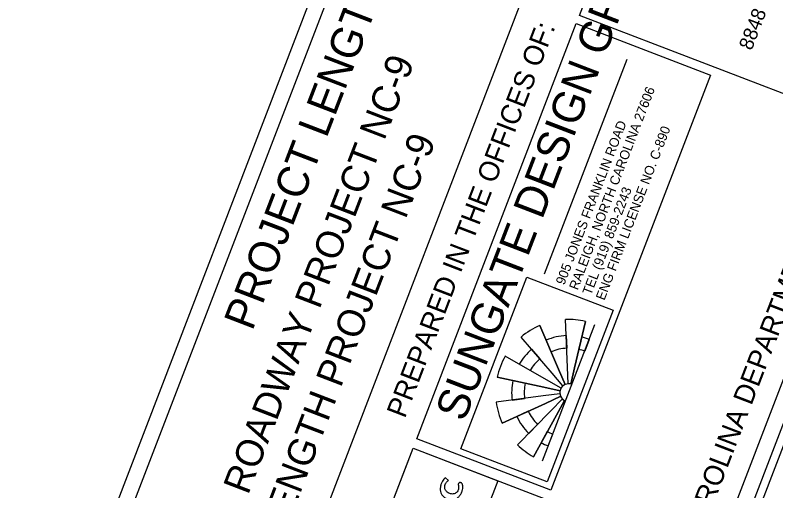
# Model space of a CAD drawing. Extents: x 1015221 to 1064345, y 619216 to 647967.
# Drawn here: x 1023380 to 1025328, y 637598 to 638817 of the extents above; entities that cross this region are included whole.
import ezdxf

# ---------------------------------------------------------------- set-up
doc = ezdxf.new("R2010")
doc.units = 0
for name, color, linetype in [('Old_Level_8', 7, 'Continuous'), ('Scratch_Level_0', 7, 'Continuous'), ('Sheet Data Field CELL', 7, 'Continuous'), ('Sheet Data Text CELL', 7, 'Continuous'), ('Sheet Plot Border Inside CELL', 7, 'Continuous'), ('Sheet Title CELL', 7, 'Continuous')]:
    doc.layers.add(name, color=color, linetype=linetype)

msp = doc.modelspace()

# ---------------------------------------------------------------- linework, layer by layer
at = {"layer": 'Scratch_Level_0'}
msp.add_lwpolyline([(1024162.8, 637091.4), (1024399.4, 637707.4), (1024616.1, 637624.1), (1024379.4, 637008.1)], close=True, dxfattribs=at)
at = {"layer": 'Sheet Data Text CELL'}
for p, q in [((1024736.3, 638154.5), (1024947.4, 638704)), ((1024772.1, 637909.9), (1024724, 638022)), ((1024724, 638022), (1024772.1, 637909.9)), ((1024730.7, 637674.8), (1024865.1, 638024.7)), ((1024795.1, 637915.2), (1024790, 638037)), ((1024795.1, 637915.2), (1024790, 638037)), ((1024812.8, 637913.5), (1024840.7, 638032.2)), ((1024840.7, 638032.2), (1024812.8, 637913.5)), ((1024755.3, 637899.5), (1024676.1, 637992.2)), ((1024755.3, 637899.5), (1024676.1, 637992.2)), ((1024753, 637954.4), (1024740.3, 637984.1)), ((1024791.8, 637995.8), (1024793.1, 637963.6)), ((1024823.9, 637960.7), (1024831.2, 637992)), ((1024850.3, 637986.2), (1024838.8, 637956.1)), ((1024702.9, 637960.8), (1024723.9, 637936.3)), ((1024741.1, 637882.3), (1024635.4, 637943)), ((1024741.1, 637882.3), (1024635.4, 637943)), ((1024699.1, 637906.5), (1024671.1, 637922.5)), ((1024772.1, 637909.9), (1024789, 637870.6)), ((1024789, 637870.6), (1024772.1, 637909.9)), ((1024796.9, 637872.4), (1024795.1, 637915.2)), ((1024796.9, 637872.4), (1024795.1, 637915.2)), ((1024812.8, 637913.5), (1024803.1, 637871.8)), ((1024803.1, 637871.8), (1024812.8, 637913.5)), ((1024733.9, 637863.6), (1024614.7, 637889.3)), ((1024614.7, 637889.3), (1024733.9, 637863.6)), ((1024778.3, 637861), (1024741.1, 637882.3)), ((1024778.3, 637861), (1024741.1, 637882.3)), ((1024783.2, 637867), (1024755.3, 637899.5)), ((1024783.2, 637867), (1024755.3, 637899.5)), ((1024686.5, 637873.8), (1024655, 637880.6)), ((1024733.9, 637863.6), (1024775.8, 637854.5)), ((1024775.8, 637854.5), (1024733.9, 637863.6)), ((1024775.4, 637846.8), (1024732.9, 637841.2)), ((1024775.4, 637846.8), (1024732.9, 637841.2)), ((1024732.9, 637841.2), (1024612.1, 637825.5)), ((1024732.9, 637841.2), (1024612.1, 637825.5)), ((1024653, 637830.8), (1024684.9, 637835)), ((1024738.4, 637822.3), (1024777.3, 637840.3)), ((1024777.3, 637840.3), (1024738.4, 637822.3)), ((1024782, 637833.6), (1024752, 637803)), ((1024782, 637833.6), (1024752, 637803)), ((1024766.3, 637792.4), (1024787, 637829.9)), ((1024787, 637829.9), (1024766.3, 637792.4)), ((1024738.4, 637822.3), (1024627.7, 637771.3)), ((1024627.7, 637771.3), (1024738.4, 637822.3)), ((1024694.4, 637802.1), (1024665.2, 637788.6)), ((1024752, 637803), (1024666.7, 637715.9)), ((1024752, 637803), (1024666.7, 637715.9)), ((1024766.3, 637792.4), (1024707.5, 637685.6)), ((1024707.5, 637685.6), (1024766.3, 637792.4)), ((1024695.6, 637745.4), (1024718.1, 637768.4)), ((1024742.9, 637749.9), (1024727.4, 637721.7)), ((1024745.5, 637713.3), (1024757, 637743.4)), ((1024490.3, 637625), (1024482.3, 637631.8))]:
    msp.add_line(p, q, dxfattribs=at)
for points in [[(1024825.5, 638816.3), (1025062.2, 639432.5), (1025713.1, 639182.4), (1025476.4, 638566.2)], [(1024408.7, 637731.4), (1024817.4, 638795.4), (1025160.7, 638663.5), (1024751.9, 637599.5)], [(1024521.6, 637705.7), (1024690.5, 638145.5), (1024911.4, 638060.7), (1024742.5, 637620.9)], [(1024162.7, 637091.2), (1024399.4, 637707.4), (1025050.3, 637457.3), (1024813.6, 636841.1)]]:
    msp.add_lwpolyline(points, close=True, dxfattribs=at)
for radius, start, end in [(187.4, 113.2233, 130.5211), (187.4, 113.2233, 130.5211), (187.4, 76.8097, 92.4104), (187.4, 76.8097, 92.4104), (146.2, 92.4104, 113.2233), (146.2, 92.4104, 113.2233), (146.2, 68.983, 76.8097), (146.2, 68.983, 76.8097), (146.2, 130.5211, 150.1448), (146.2, 130.5211, 150.1448), (113.9, 92.4104, 113.2233), (113.9, 92.4104, 113.2233), (113.9, 68.983, 76.8097), (113.9, 68.983, 76.8097), (187.4, 150.1448, 167.8212), (187.4, 150.1448, 167.8212), (113.9, 130.5211, 150.1448), (113.9, 130.5211, 150.1448), (146.2, 167.8212, 187.445), (146.2, 167.8212, 187.445), (113.9, 167.8212, 187.445), (113.9, 167.8212, 187.445), (22.7, 68.983, 248.983), (22.7, 113.2233, 130.5211), (22.7, 76.8097, 92.4104), (22.7, 187.445, 204.7427), (22.7, 150.1448, 167.8212), (187.4, 187.445, 204.7427), (187.4, 187.445, 204.7427), (22.7, 225.5557, 241.1563), (146.2, 204.7427, 225.5557), (146.2, 204.7427, 225.5557), (113.9, 204.7427, 225.5557), (113.9, 204.7427, 225.5557), (113.9, 241.1563, 248.983), (113.9, 241.1563, 248.983), (187.4, 225.5557, 241.1563), (187.4, 225.5557, 241.1563), (146.2, 241.1563, 248.983), (146.2, 241.1563, 248.983)]:
    msp.add_arc((1024797.9, 637849.7), radius, start, end, dxfattribs=at)
msp.add_open_spline([(1024482.3, 637631.8), (1024481.1, 637630.8), (1024478.3, 637628.5), (1024474.6, 637623.3), (1024471.1, 637616.4), (1024469, 637608.4), (1024468.6, 637600.2), (1024470.3, 637592.6), (1024474.1, 637586.1), (1024479.4, 637581), (1024486.1, 637577.3), (1024493.5, 637575.1), (1024500.9, 637575.1), (1024507.2, 637576.8), (1024513.4, 637580.2), (1024519.3, 637585.8), (1024523.7, 637593.4), (1024526, 637601), (1024526.8, 637607.8), (1024526.4, 637613.5), (1024524.6, 637617.8), (1024521.7, 637619.1), (1024519.5, 637619.7), (1024517.6, 637618.7), (1024516.1, 637617.6), (1024515.4, 637616), (1024514.9, 637613.6), (1024515.8, 637611), (1024515.9, 637607.6), (1024516.2, 637604.2), (1024514.9, 637600), (1024512.9, 637595.8), (1024509, 637592.5), (1024504.7, 637590.6), (1024500, 637589.6), (1024495.3, 637590.5), (1024490.7, 637591.6), (1024486.8, 637594.5), (1024483.5, 637597.7), (1024481.3, 637601.4), (1024480.2, 637605.6), (1024480.2, 637609.9), (1024481.5, 637614.5), (1024483.6, 637618.8), (1024486.6, 637622.5), (1024489.1, 637624.2), (1024490.3, 637625)], degree=3, dxfattribs=at)
at = {"layer": 'Sheet Plot Border Inside CELL'}
msp.add_lwpolyline([(1023304.8, 632396.8), (1028086.2, 644841.8), (1020206.9, 647869.1), (1015425.5, 635424)], close=True, dxfattribs=at)
at = {"layer": 'Sheet Title CELL'}
for p, q in [((1022495.1, 634584.7), (1026569.3, 645189)), ((1023508, 637109.4), (1024598.3, 639947.1)), ((1023914.2, 636867.6), (1025061.8, 639854.7))]:
    msp.add_line(p, q, dxfattribs=at)
for points in [[(1023756.2, 633628.8), (1028002.6, 644681.1)], [(1024852.2, 636592.9), (1025942.5, 639430.7)]]:
    msp.add_lwpolyline(points, dxfattribs=at)

# ---------------------------------------------------------------- texts
at = {"layer": 'Old_Level_8'}
for s, p in [('FOR THE NORTH CAROLINA DEPARTMENT OF TRANSPORTATION', (1024922, 636920.4)), ('PREPARED IN THE OFFICES OF:', (1024378.2, 637781.9))]:
    msp.add_text(s, height=51.593, rotation=68.983, dxfattribs=at).set_placement(p)
at = {"layer": 'Sheet Data Field CELL'}
for s, p in [('LENGTH ROADWAY PROJECT NC-9 ', (1023831.1, 637207)), ('TOTAL LENGTH PROJECT NC-9', (1023951, 637175.7))]:
    msp.add_text(s, height=70.001, rotation=68.983, dxfattribs=at).set_placement(p)
at = {"layer": 'Sheet Data Text CELL'}
for s, height, p in [('SUNGATE DESIGN GROUP, P.A.', 81.268, (1024530.3, 637772.4)), ('8848 RED OAK BLVD', 36.237, (1025266.3, 638724.7)), ('RALEIGH, NORTH CAROLINA 27606', 24.423, (1024820.8, 638110.9)), ('905 JONES FRANKLIN ROAD', 24.423, (1024786.6, 638124)), ('ENG FIRM LICENSE NO. C-890', 24.423, (1024889.2, 638084.6)), ('TEL (919) 859-2243', 24.423, (1024855, 638097.8))]:
    msp.add_text(s, height=height, rotation=68.983, dxfattribs=at).set_placement(p)
at = {"layer": 'Sheet Title CELL'}
msp.add_text('PROJECT LENGTH', height=79.997, rotation=68.983, dxfattribs=at).set_placement((1023987.5, 638005.8))

doc.saveas('drawing.dxf')
